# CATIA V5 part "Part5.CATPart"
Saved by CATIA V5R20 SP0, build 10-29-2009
Part number: 1DIN7984516_DIN 7984 - M5 x 16 --- 16C
Revision: ANY
Definition: UNKNOWN
Nomenclature: 1DIN7984516_DIN 7984 - M5 x 16 --- 16C
Source: Unknown
Bounding box of the stored display mesh (mm): x 0 to 19.5, y -4.25 to 4.25, z -4.25 to 4.25
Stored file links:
  C:\Users\Utente\Desktop\IO LAVORO\3D X SITO CF\CUMSA\3D files PW\pw081225\pw081225_injection\Part5.CATPart
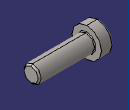
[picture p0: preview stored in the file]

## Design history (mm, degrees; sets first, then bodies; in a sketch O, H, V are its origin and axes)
Body1 "Hex" (main body)
  Solid1: solid without history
